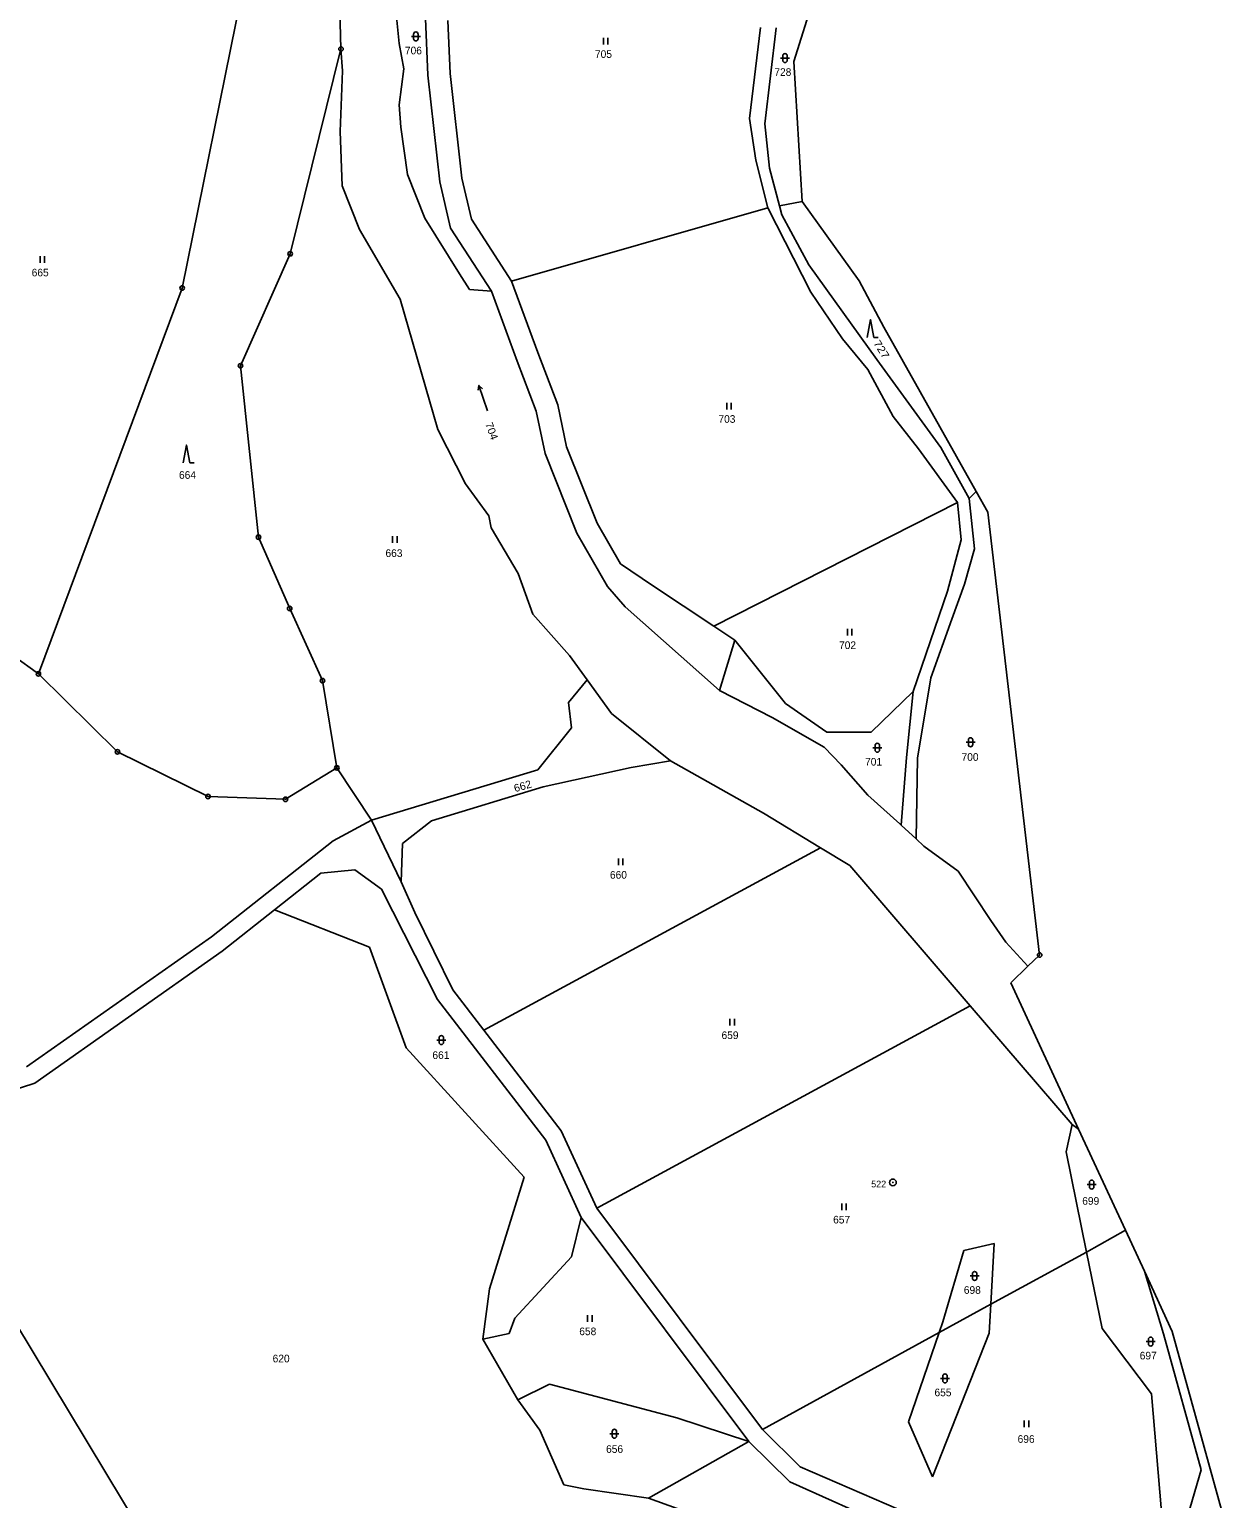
# Model space of a CAD drawing. Extents: x -719614 to -717765, y -1095834 to -1093862.
# Drawn here: x -718372.3 to -718104.7, y -1095029.2 to -1094701.4 of the extents above; entities that cross this region are included whole.
import ezdxf
from ezdxf.enums import TextEntityAlignment as Align

# ---------------------------------------------------------------- set-up
doc = ezdxf.new("R2010")
doc.units = 0
doc.header["$LTSCALE"] = 0.68
for name, color, linetype, lineweight in [('1', 7, 'Continuous', 25), ('3', 7, 'Continuous', 25), ('8', 7, 'Continuous', 25)]:
    doc.layers.add(name, color=color, linetype=linetype, lineweight=lineweight)
doc.layers.add('2', color=7, linetype='Continuous')

msp = doc.modelspace()

# ---------------------------------------------------------------- linework, layer by layer
at = {"layer": '1'}
for p, q in [((-718194.83, -1094686.56), (-718201.68, -1094708.56)), ((-718323.58, -1094687.09), (-718338.19, -1094759.09)), ((-718302.75, -1094705.74), (-718303.17, -1094690.28)), ((-718290.93, -1094692.81), (-718289.77, -1094704.51)), ((-718283.36, -1094711.58), (-718283.9, -1094698.94)), ((-718278.88, -1094699.39), (-718278.37, -1094711.2)), ((-718211.58, -1094721.22), (-718209.14, -1094700.98)), ((-718208.16, -1094722.43), (-718205.66, -1094701)), ((-718302.75, -1094705.74), (-718314.09, -1094751.44)), ((-718302.43, -1094710.63), (-718302.75, -1094705.74)), ((-718289.77, -1094704.51), (-718288.75, -1094710.15)), ((-718201.68, -1094708.56), (-718199.85, -1094739.79)), ((-718302.96, -1094724.13), (-718302.43, -1094710.63)), ((-718288.75, -1094710.15), (-718289.76, -1094718.24)), ((-718280.72, -1094735.39), (-718283.36, -1094711.58)), ((-718278.37, -1094711.2), (-718275.78, -1094734.54)), ((-718289.76, -1094718.24), (-718289.42, -1094723.22)), ((-718210.19, -1094730.56), (-718211.58, -1094721.22)), ((-718207.16, -1094732.34), (-718208.16, -1094722.43)), ((-718302.49, -1094736.31), (-718302.96, -1094724.13)), ((-718289.42, -1094723.22), (-718287.88, -1094733.75)), ((-718207.5, -1094741.19), (-718210.19, -1094730.56)), ((-718204.94, -1094740.76), (-718207.16, -1094732.34)), ((-718287.88, -1094733.75), (-718284.03, -1094743.49)), ((-718278.3, -1094745.73), (-718280.72, -1094735.39)), ((-718275.78, -1094734.54), (-718273.63, -1094743.75)), ((-718298.64, -1094746.06), (-718302.49, -1094736.31)), ((-718207.5, -1094741.19), (-718264.7, -1094757.57)), ((-718197.92, -1094760.02), (-718207.5, -1094741.19)), ((-718199.85, -1094739.79), (-718204.94, -1094740.76)), ((-718204.94, -1094740.76), (-718204.41, -1094742.75)), ((-718199.85, -1094739.79), (-718187.17, -1094757.48)), ((-718284.03, -1094743.49), (-718276.32, -1094755.94)), ((-718273.63, -1094743.75), (-718264.7, -1094757.57)), ((-718204.41, -1094742.75), (-718198.38, -1094753.94)), ((-718289.54, -1094761.6), (-718298.64, -1094746.06)), ((-718269.2, -1094759.82), (-718278.3, -1094745.73)), ((-718314.09, -1094751.44), (-718325.17, -1094776.43)), ((-718198.38, -1094753.94), (-718183.18, -1094775.03)), ((-718276.32, -1094755.94), (-718274.1, -1094759.45)), ((-718264.7, -1094757.57), (-718258.8, -1094773.45)), ((-718187.17, -1094757.48), (-718181.65, -1094767.8)), ((-718338.19, -1094759.09), (-718370.26, -1094845.2)), ((-718281.15, -1094790.66), (-718289.54, -1094761.6)), ((-718274.1, -1094759.45), (-718269.2, -1094759.82)), ((-718269.2, -1094759.82), (-718263.41, -1094775.4)), ((-718190.84, -1094770.46), (-718197.92, -1094760.02)), ((-718161.02, -1094804.5), (-718181.65, -1094767.8)), ((-718185.24, -1094777.28), (-718190.84, -1094770.46)), ((-718258.8, -1094773.45), (-718254.38, -1094785.14)), ((-718183.18, -1094775.03), (-718168.91, -1094794.64)), ((-718325.17, -1094776.43), (-718321.15, -1094814.7)), ((-718263.41, -1094775.4), (-718259.19, -1094786.55)), ((-718179.56, -1094787.76), (-718185.24, -1094777.28)), ((-718259.19, -1094786.55), (-718257.22, -1094795.98)), ((-718254.38, -1094785.14), (-718252.41, -1094794.53)), ((-718173.91, -1094794.94), (-718179.56, -1094787.76)), ((-718274.97, -1094802.75), (-718281.15, -1094790.66)), ((-718252.41, -1094794.53), (-718245.62, -1094811.59)), ((-718168.91, -1094794.64), (-718162.58, -1094806.06)), ((-718257.22, -1094795.98), (-718250.13, -1094813.78)), ((-718165.2, -1094806.92), (-718173.91, -1094794.94)), ((-718269.77, -1094809.96), (-718274.97, -1094802.75)), ((-718162.58, -1094806.06), (-718161.02, -1094804.5)), ((-718158.45, -1094809.08), (-718161.02, -1094804.5)), ((-718219.59, -1094834.57), (-718165.2, -1094806.92)), ((-718164.37, -1094815.27), (-718165.2, -1094806.92)), ((-718162.58, -1094806.06), (-718161.4, -1094817.3)), ((-718269.23, -1094812.64), (-718269.77, -1094809.96)), ((-718146.87, -1094907.94), (-718158.45, -1094809.08)), ((-718414, -1094813.69), (-718370.26, -1094845.2)), ((-718263.19, -1094822.76), (-718269.23, -1094812.64)), ((-718250.13, -1094813.78), (-718243.26, -1094825.68)), ((-718245.62, -1094811.59), (-718240.41, -1094820.61)), ((-718321.15, -1094814.7), (-718314.19, -1094830.6)), ((-718167.4, -1094826.73), (-718164.37, -1094815.27)), ((-718161.4, -1094817.3), (-718163.67, -1094825.16)), ((-718240.41, -1094820.61), (-718233.25, -1094825.48)), ((-718259.97, -1094831.86), (-718263.19, -1094822.76)), ((-718243.26, -1094825.68), (-718239.32, -1094830.2)), ((-718233.25, -1094825.48), (-718219.59, -1094834.57)), ((-718175.11, -1094849.14), (-718167.4, -1094826.73)), ((-718163.67, -1094825.16), (-718166.48, -1094833.02)), ((-718314.19, -1094830.6), (-718306.87, -1094846.7)), ((-718239.32, -1094830.2), (-718218.29, -1094848.9)), ((-718251.8, -1094841.13), (-718259.97, -1094831.86)), ((-718166.48, -1094833.02), (-718171.15, -1094846.1)), ((-718219.59, -1094834.57), (-718214.89, -1094837.7)), ((-718214.89, -1094837.7), (-718218.29, -1094848.9)), ((-718203.6, -1094851.81), (-718214.89, -1094837.7)), ((-718247.85, -1094846.55), (-718251.8, -1094841.13)), ((-718370.26, -1094845.2), (-718352.63, -1094862.58)), ((-718306.87, -1094846.7), (-718303.68, -1094866.18)), ((-718251.97, -1094851.6), (-718247.85, -1094846.55)), ((-718242.41, -1094854.03), (-718247.85, -1094846.55)), ((-718171.15, -1094846.1), (-718174.13, -1094864.01)), ((-718218.29, -1094848.9), (-718206.56, -1094854.96)), ((-718175.11, -1094849.14), (-718184.45, -1094858.21)), ((-718176.57, -1094863.83), (-718175.11, -1094849.14)), ((-718251.3, -1094857.26), (-718251.97, -1094851.6)), ((-718194.35, -1094858.17), (-718203.6, -1094851.81)), ((-718229.22, -1094864.57), (-718242.41, -1094854.03)), ((-718206.56, -1094854.96), (-718194.98, -1094861.55)), ((-718258.87, -1094866.59), (-718251.3, -1094857.26)), ((-718184.45, -1094858.21), (-718194.35, -1094858.17)), ((-718352.63, -1094862.58), (-718332.41, -1094872.57)), ((-718194.98, -1094861.55), (-718191.13, -1094865.53)), ((-718315.12, -1094873.19), (-718303.68, -1094866.18)), ((-718303.68, -1094866.18), (-718295.93, -1094877.87)), ((-718295.93, -1094877.87), (-718258.87, -1094866.59)), ((-718257.67, -1094870.41), (-718238.03, -1094866.08)), ((-718238.03, -1094866.08), (-718229.22, -1094864.57)), ((-718208.51, -1094876.25), (-718229.22, -1094864.57)), ((-718191.13, -1094865.53), (-718185.23, -1094872.26)), ((-718177.76, -1094878.94), (-718176.57, -1094863.83)), ((-718174.13, -1094864.01), (-718174.44, -1094882.01)), ((-718332.41, -1094872.57), (-718315.12, -1094873.19)), ((-718282.54, -1094877.97), (-718257.67, -1094870.41)), ((-718185.23, -1094872.26), (-718178.07, -1094878.65)), ((-718195.75, -1094884), (-718208.51, -1094876.25)), ((-718304.53, -1094882.49), (-718295.93, -1094877.87)), ((-718295.93, -1094877.87), (-718289.32, -1094891.57)), ((-718289, -1094883.03), (-718282.54, -1094877.97)), ((-718178.07, -1094878.65), (-718177.76, -1094878.94)), ((-718177.76, -1094878.94), (-718174.44, -1094882.01)), ((-718331.65, -1094903.88), (-718304.53, -1094882.49)), ((-718289.32, -1094891.57), (-718289, -1094883.03)), ((-718174.44, -1094882.01), (-718172.69, -1094883.62)), ((-718270.87, -1094924.73), (-718195.75, -1094884)), ((-718189.21, -1094887.97), (-718195.75, -1094884)), ((-718172.69, -1094883.62), (-718165.03, -1094889.19)), ((-718307.22, -1094889.7), (-718317.56, -1094897.86)), ((-718299.63, -1094888.95), (-718307.22, -1094889.7)), ((-718293.75, -1094893.25), (-718299.63, -1094888.95)), ((-718162.36, -1094919.28), (-718189.21, -1094887.97)), ((-718165.03, -1094889.19), (-718157.74, -1094900.25)), ((-718289.32, -1094891.57), (-718286.26, -1094898.42)), ((-718281.22, -1094917.86), (-718293.75, -1094893.25)), ((-718317.56, -1094897.86), (-718329.24, -1094907.07)), ((-718317.56, -1094897.86), (-718296.38, -1094906.22)), ((-718286.26, -1094898.42), (-718277.82, -1094915.71)), ((-718157.74, -1094900.25), (-718154.42, -1094905.05)), ((-718372.9, -1094932.91), (-718331.65, -1094903.88)), ((-718296.38, -1094906.22), (-718288.2, -1094928.62)), ((-718154.42, -1094905.05), (-718149.47, -1094910.43)), ((-718329.24, -1094907.07), (-718371.08, -1094936.52)), ((-718149.47, -1094910.43), (-718146.87, -1094907.94)), ((-718153.3, -1094914.11), (-718149.47, -1094910.43)), ((-718277.82, -1094915.71), (-718270.87, -1094924.73)), ((-718138.17, -1094946.79), (-718153.3, -1094914.11)), ((-718257.06, -1094949.23), (-718281.22, -1094917.86)), ((-718162.36, -1094919.28), (-718245.69, -1094964.46)), ((-718139.65, -1094945.78), (-718162.36, -1094919.28)), ((-718270.87, -1094924.73), (-718253.61, -1094947.15)), ((-718288.2, -1094928.62), (-718261.87, -1094957.49)), ((-718411.97, -1094929.43), (-718310.27, -1095097.96)), ((-718371.08, -1094936.52), (-718383.03, -1094940.46)), ((-718253.61, -1094947.15), (-718245.69, -1094964.46)), ((-718140.97, -1094951.84), (-718139.65, -1094945.78)), ((-718138.17, -1094946.79), (-718139.65, -1094945.78)), ((-718127.74, -1094969.32), (-718138.17, -1094946.79)), ((-718249.15, -1094966.51), (-718257.06, -1094949.23)), ((-718136.4, -1094974.25), (-718140.97, -1094951.84)), ((-718261.87, -1094957.49), (-718269.61, -1094982.43)), ((-718245.69, -1094964.46), (-718208.73, -1095013.83)), ((-718251.31, -1094975.29), (-718249.15, -1094966.51)), ((-718211.75, -1095016.47), (-718249.15, -1094966.51)), ((-718136.4, -1094974.25), (-718127.74, -1094969.32)), ((-718123.5, -1094978.48), (-718127.74, -1094969.32)), ((-718168.44, -1094989.77), (-718163.75, -1094973.88)), ((-718163.75, -1094973.88), (-718157.02, -1094972.34)), ((-718157.02, -1094972.34), (-718157.76, -1094985.86)), ((-718136.4, -1094974.25), (-718157.76, -1094985.86)), ((-718132.93, -1094991.26), (-718136.4, -1094974.25)), ((-718264, -1094988.95), (-718251.31, -1094975.29)), ((-718119.2, -1094992.47), (-718123.5, -1094978.48)), ((-718117.27, -1094991.94), (-718123.5, -1094978.48)), ((-718269.61, -1094982.43), (-718271.12, -1094993.63)), ((-718157.76, -1094985.86), (-718169.26, -1094992.17)), ((-718158.11, -1094992.34), (-718157.76, -1094985.86)), ((-718265.25, -1094992.38), (-718264, -1094988.95)), ((-718169.26, -1094992.17), (-718168.44, -1094989.77)), ((-718121.9, -1095005.89), (-718132.93, -1094991.26)), ((-718271.12, -1094993.63), (-718265.25, -1094992.38)), ((-718263.33, -1095007.18), (-718271.12, -1094993.63)), ((-718169.26, -1094992.17), (-718208.73, -1095013.83)), ((-718169.26, -1094992.17), (-718176.12, -1095012.1)), ((-718170.77, -1095024.38), (-718158.11, -1094992.34)), ((-718110.82, -1095022.82), (-718119.2, -1094992.47)), ((-718104.71, -1095037.45), (-718117.27, -1094991.94)), ((-718263.33, -1095007.18), (-718256.23, -1095003.68)), ((-718256.23, -1095003.68), (-718227.85, -1095011.24)), ((-718258.4, -1095014), (-718263.33, -1095007.18)), ((-718119.07, -1095039.08), (-718121.9, -1095005.89)), ((-718253.01, -1095026.17), (-718258.4, -1095014)), ((-718227.85, -1095011.24), (-718211.75, -1095016.47)), ((-718208.73, -1095013.83), (-718200.3, -1095022.15)), ((-718176.12, -1095012.1), (-718170.77, -1095024.38)), ((-718211.75, -1095016.47), (-718234.15, -1095029.17)), ((-718202.58, -1095025.52), (-718211.75, -1095016.47)), ((-718200.3, -1095022.15), (-718175.54, -1095032.85)), ((-718115.69, -1095039.42), (-718110.82, -1095022.82)), ((-718248.58, -1095027.09), (-718253.01, -1095026.17)), ((-718234.15, -1095029.17), (-718248.58, -1095027.09)), ((-718180.05, -1095035.63), (-718202.58, -1095025.52)), ((-718234.15, -1095029.17), (-718219.5, -1095034.4))]:
    msp.add_line(p, q, dxfattribs=at)
at = {"layer": '3'}
for p, q in [((-718287.051, -1094702.951), (-718285.049, -1094702.951)), ((-718286.551, -1094702.451), (-718286.551, -1094703.452)), ((-718285.549, -1094703.452), (-718285.549, -1094702.451)), ((-718244.201, -1094704.75), (-718244.201, -1094703.25)), ((-718243.2, -1094704.75), (-718243.2, -1094703.25)), ((-718204.691, -1094707.761), (-718202.689, -1094707.761)), ((-718204.191, -1094707.261), (-718204.191, -1094708.262)), ((-718203.189, -1094708.262), (-718203.189, -1094707.261)), ((-718369.901, -1094753.5), (-718369.901, -1094752)), ((-718368.9, -1094753.5), (-718368.9, -1094752)), ((-718183.89, -1094770.12), (-718182.894, -1094770.12)), ((-718271.984, -1094780.804), (-718271.192, -1094781.565)), ((-718216.691, -1094786.18), (-718216.691, -1094784.68)), ((-718215.69, -1094786.18), (-718215.69, -1094784.68)), ((-718336.49, -1094798.13), (-718335.494, -1094798.13)), ((-718291.241, -1094815.94), (-718291.241, -1094814.44)), ((-718290.24, -1094815.94), (-718290.24, -1094814.44)), ((-718189.771, -1094836.66), (-718189.771, -1094835.16)), ((-718188.77, -1094836.66), (-718188.77, -1094835.16)), ((-718162.781, -1094859.941), (-718162.781, -1094860.942)), ((-718161.779, -1094860.942), (-718161.779, -1094859.941)), ((-718184.091, -1094861.681), (-718182.089, -1094861.681)), ((-718183.591, -1094861.181), (-718183.591, -1094862.182)), ((-718182.589, -1094862.182), (-718182.589, -1094861.181)), ((-718163.281, -1094860.441), (-718161.279, -1094860.441)), ((-718240.861, -1094887.91), (-718240.861, -1094886.41)), ((-718239.86, -1094887.91), (-718239.86, -1094886.41)), ((-718215.981, -1094923.7), (-718215.981, -1094922.2)), ((-718214.98, -1094923.7), (-718214.98, -1094922.2)), ((-718281.351, -1094926.921), (-718279.349, -1094926.921)), ((-718280.851, -1094926.421), (-718280.851, -1094927.422)), ((-718279.849, -1094927.422), (-718279.849, -1094926.421)), ((-718135.761, -1094958.661), (-718135.761, -1094959.662)), ((-718134.759, -1094959.662), (-718134.759, -1094958.661)), ((-718136.261, -1094959.161), (-718134.259, -1094959.161)), ((-718191.041, -1094964.86), (-718191.041, -1094963.36)), ((-718190.04, -1094964.86), (-718190.04, -1094963.36)), ((-718162.381, -1094979.561), (-718160.379, -1094979.561)), ((-718161.881, -1094979.061), (-718161.881, -1094980.062)), ((-718160.879, -1094980.062), (-718160.879, -1094979.061)), ((-718247.731, -1094989.79), (-718247.731, -1094988.29)), ((-718246.73, -1094989.79), (-718246.73, -1094988.29)), ((-718123.091, -1094994.201), (-718121.089, -1094994.201)), ((-718122.591, -1094993.701), (-718122.591, -1094994.702)), ((-718121.589, -1094994.702), (-718121.589, -1094993.701)), ((-718169.001, -1095002.421), (-718166.999, -1095002.421)), ((-718168.501, -1095001.921), (-718168.501, -1095002.922)), ((-718167.499, -1095002.922), (-718167.499, -1095001.921)), ((-718242.251, -1095014.281), (-718242.251, -1095015.282)), ((-718241.249, -1095015.282), (-718241.249, -1095014.281)), ((-718150.291, -1095013.32), (-718150.291, -1095011.82)), ((-718149.29, -1095013.32), (-718149.29, -1095011.82)), ((-718242.751, -1095014.781), (-718240.749, -1095014.781))]:
    msp.add_line(p, q, dxfattribs=at)
for points in [[(-718183.89, -1094770.12), (-718184.64, -1094766.12), (-718185.39, -1094770.12)], [(-718270.031, -1094786.478), (-718271.984, -1094780.804), (-718272.14, -1094781.892)], [(-718336.49, -1094798.13), (-718337.24, -1094794.13), (-718337.99, -1094798.13)]]:
    msp.add_lwpolyline(points, dxfattribs=at)
for centre, start, end in [((-718286.05, -1094702.4509), 0, 180), ((-718286.05, -1094703.4509), 180, 359.98789), ((-718203.69, -1094707.2609), 0, 180), ((-718203.69, -1094708.2609), 180, 359.98789), ((-718162.28, -1094859.9409), 0, 180), ((-718183.09, -1094861.1809), 0, 180), ((-718183.09, -1094862.1809), 180, 359.98789), ((-718162.28, -1094860.9409), 180, 359.98789), ((-718280.35, -1094926.4209), 0, 180), ((-718280.35, -1094927.4209), 180, 359.98789), ((-718135.26, -1094958.6609), 0, 180), ((-718135.26, -1094959.6609), 180, 359.98789), ((-718161.38, -1094979.0609), 0, 180), ((-718161.38, -1094980.0609), 180, 359.98789), ((-718122.09, -1094993.7009), 0, 180), ((-718122.09, -1094994.7009), 180, 359.98789), ((-718168, -1095001.9209), 0, 180), ((-718168, -1095002.9209), 180, 359.98789), ((-718241.75, -1095014.2809), 0, 180), ((-718241.75, -1095015.2809), 180, 359.98789)]:
    msp.add_arc(centre, 0.5, start, end, dxfattribs=at)
at = {"layer": '8'}
for centre, radius in [((-718302.75, -1094705.7399), 0.5), ((-718302.75, -1094705.7399), 0.0303), ((-718314.09, -1094751.4399), 0.5), ((-718314.09, -1094751.4399), 0.0303), ((-718338.19, -1094759.0899), 0.5), ((-718338.19, -1094759.0899), 0.0303), ((-718325.17, -1094776.4299), 0.5), ((-718325.17, -1094776.4299), 0.0303), ((-718321.15, -1094814.6999), 0.5), ((-718321.15, -1094814.6999), 0.0303), ((-718314.19, -1094830.5999), 0.5), ((-718314.19, -1094830.5999), 0.0303), ((-718370.26, -1094845.1999), 0.5), ((-718370.26, -1094845.1999), 0.0303), ((-718306.87, -1094846.6999), 0.5), ((-718306.87, -1094846.6999), 0.0303), ((-718352.63, -1094862.5799), 0.5), ((-718352.63, -1094862.5799), 0.0303), ((-718303.68, -1094866.1799), 0.5), ((-718303.68, -1094866.1799), 0.0303), ((-718332.41, -1094872.5699), 0.5), ((-718332.41, -1094872.5699), 0.0303), ((-718315.12, -1094873.1899), 0.5), ((-718315.12, -1094873.1899), 0.0303), ((-718146.87, -1094907.9399), 0.5), ((-718146.87, -1094907.9399), 0.0303), ((-718179.61, -1094958.6798), 0.75), ((-718179.61, -1094958.6798), 0.03)]:
    msp.add_circle(centre, radius, dxfattribs=at)

# ---------------------------------------------------------------- texts
at = {"layer": '2'}
for s, p in [('706', (-718286.589, -1094706.932)), ('705', (-718244.189, -1094707.732)), ('728', (-718204.169, -1094711.742)), ('665', (-718369.869, -1094756.482)), ('703', (-718216.639, -1094789.162)), ('664', (-718336.999, -1094801.662)), ('663', (-718290.929, -1094819.102)), ('702', (-718189.729, -1094839.642)), ('700', (-718162.399, -1094864.592)), ('701', (-718183.929, -1094865.662)), ('660', (-718240.849, -1094890.892)), ('659', (-718215.949, -1094926.682)), ('661', (-718280.459, -1094931.132)), ('699', (-718135.469, -1094963.662)), ('657', (-718191.049, -1094967.842)), ('698', (-718161.889, -1094983.542)), ('658', (-718247.689, -1094992.772)), ('620', (-718316.109, -1094998.832)), ('697', (-718122.649, -1094998.182)), ('655', (-718168.439, -1095006.402)), ('656', (-718241.709, -1095019.042)), ('696', (-718149.889, -1095016.792))]:
    msp.add_text(s, height=1.7, dxfattribs=at).set_placement(p, align=Align.CENTER)
for s, rotation, width, p in [('727', 302, 1.15, (-718182.8839, -1094773.2386)), ('704', 290, 1.05, (-718269.9213, -1094791.2863)), ('662', 16, 1.05, (-718261.9873, -1094871.0587))]:
    msp.add_text(s, height=1.7, rotation=rotation, dxfattribs=dict(at, width=width)).set_placement(p, align=Align.CENTER)
at = {"layer": '8'}
msp.add_text('522', height=1.5, dxfattribs=at).set_placement((-718181.109, -1094959.797), align=Align.RIGHT)

doc.saveas('drawing.dxf')
